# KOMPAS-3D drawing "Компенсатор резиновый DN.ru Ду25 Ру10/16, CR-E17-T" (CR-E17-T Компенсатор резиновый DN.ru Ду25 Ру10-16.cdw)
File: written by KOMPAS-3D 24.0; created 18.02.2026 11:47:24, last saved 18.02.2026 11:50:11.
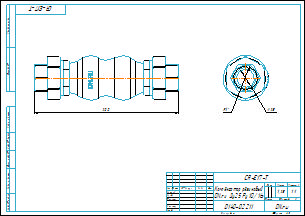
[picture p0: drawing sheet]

Document properties: Типовые: Типовые; Автор: DN.RU; Форматы листов документа: A3; Полное имя файла: CR-E17-T Компенсатор резиновый DN.ru Ду25 Ру10-16.m3d; Масса: 1.25; Наименование: Компенсатор резиновый DN.ru Ду25 Ру10/16; Количество листов документа: 1; Комментарий: D140-02211; Примечание: D140-02211

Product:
- Body: Твердое тело1  | qty 1
    Масса: 2.292804
- Part/product: Компенсатор резиновый DN.ru Ду25 Ру10/16  | designation CR-E17-T
    Масса: 1.25
    Раздел спецификации: Прочие изделия
    Форматы листов документа: A3
    Комментарий: D140-02211
    Примечание: D140-02211
    additional columns: Типовые

Views: Вид 1, Справа, Проекционный вид 2
Referenced files in D:\Работа\Компенсаторы\CR-Е17-T Компенсатор резиновый DN.ru Ду15-80\DN25\: CR-E17-T Компенсатор резиновый DN.ru Ду25 Ру10-16.m3d, CR-E17-T Компенсатор резиновый DN.ru Ду25 Ру10-16.cdw
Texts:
  Линейный размер
  CR-E17-T
  Диаметральный размер
  Компенсатор резиновый
  DN.ru Ду25 Ру10/16
  Твердое тело1
  Компенсатор резиновый DN.ru Ду25 Ру10/16
  CR-E17-T Компенсатор резиновый DN.ru Ду25 Ру10/16
Dimensions and other numbers on the sheet: 0; 3; 2; 4; 200; 25; 1:1; 1; 1,25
